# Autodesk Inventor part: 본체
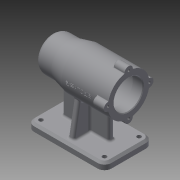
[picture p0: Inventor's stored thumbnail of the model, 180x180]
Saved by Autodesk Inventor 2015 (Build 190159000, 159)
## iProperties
Created: 2019-07
Part Number: 본체
Material: 일반
Document SubType Name: Modeling
Designer: now
Density: 1 g/cm^3
Appearance: 기본값
Author: now
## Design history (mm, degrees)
sketch "스케치1"
  geometry: L1 (-56, 35)-(56, 35); L2 (56, 35)-(56, -35); L3 (56, -35)-(-56, -35); L4 (-56, -35)-(-56, 35); L5 (-56, 35)-(56, -35); L6 (56, 35)-(-56, -35); 1 further point
  constraints: 12 end point, 2 midpoint, 2 parallel, 1 horizontal, 1 perpendicular
  dimensions: "d0" = 70 distance of L1.end L2.end; "d1" = 112 distance of L2.end L3.end
extrude "돌출1" new body sketch "스케치1" distance "d2" = 10; taper "d3" = 0 deg
sketch "스케치2"
  geometry: L1 (-46, 25)-(46, 25); L2 (46, 25)-(46, -25); L3 (46, -25)-(-46, -25); L4 (-46, -25)-(-46, 25); L5 (-46, 25)-(46, -25); L6 (46, 25)-(-46, -25); 1 further point
  constraints: 12 end point, 2 midpoint, 2 parallel, 1 horizontal, 1 perpendicular
  dimensions: "d4" = 92 distance of L2.end L3.end; "d5" = 50 distance of L1.end L2.end
hole "구멍1" sketch "스케치2" at (-46, -25), (46, -25), (46, 25), (-46, 25) diameter "d6" = 6; stored, may be unused: countersink angle "d10" = 90 deg, drill point angle "d12" = 118 deg; dims "d7" = 6, "d8" = 4, "d9" = 2, "d11" = 8
fillet "모깎기1" dims "d13" = 10
sketch "스케치3"
  geometry: L1 (-56, 25)-(-56, -25) reference; L2 (-46, -35)-(46, -35) reference; L3 (56, -25)-(56, 25) reference; L4 (-4, -28)-(4, -28); L5 (4, -28)-(4, 28); L6 (4, 28)-(-4, 28); L7 (-4, 28)-(-4, -28); L8 (-4, -28)-(4, 28); L9 (4, -28)-(-4, 28); L10 (-31, 4)-(31, -4); L11 (-36, 4)-(31, 4); L12 (31, 4)-(31, -4); L13 (31, -4)-(-36, -4); L14 (-36, -4)-(-36, 4); L15 (-36, 4)-(31, -4); L16 (31, 4)-(-36, -4); 2 further points
  constraints: 26 end point, 5 midpoint, 4 parallel, 2 horizontal, 2 perpendicular, 1 horizontal alignment
  dimensions: "d14" = 8 distance of L5.end L6.end; "d16" = 7 distance between parallel lines of L4 L2; "d18" = 25 distance between parallel lines of L3 L12; "d19" = 20 distance between parallel lines of L14 L1; "d20" = 8 distance of L11.end L12.end
extrude "돌출2" join sketch "스케치3" distance "d21" = 70; taper "d22" = 0 deg
node "작업 평면3"
sketch "스케치6"
  geometry: L1 (0, 0)-(0, 80); C1 r 30 at (0, 80)
  constraints: 2 end point, 1 centre point, 1 coincident, 1 vertical
  dimensions: "d29" = 80 distance of L1.start L1.end; "d30" = 60 diameter of C1
extrude "돌출4" join sketch "스케치6" distance "d31" = 67; taper "d32" = 0 deg
node "작업 평면5"
  node "작업 평면4"
sketch "스케치9"
  geometry: L1 (56, 10)-(56, 0) reference; L2 (56, 0)-(-56, 0) reference; L3 (-56, 0)-(-56, 10) reference; L4 (-56, 10)-(-31, 10) reference; L5 (-31, 10)-(-31, 50) reference; L6 (-31, 50)-(-56, 50) reference; L7 (-56, 50)-(-56, 110) reference; L8 (-56, 110)-(11, 110) reference; L9 (11, 110)-(11, 80) reference; L10 (11, 80)-(36, 80) reference; L11 (36, 80)-(36, 10) reference; L12 (36, 10)-(56, 10) reference; L13 (11, 80)-(31, 80); L14 (31, 80)-(31, 105); L15 (31, 105)-(11, 110); 1 further point
  constraints: 6 end point, 1 horizontal, 1 perpendicular
  dimensions: "d37" = 25 distance of L13.end L14.end; "d38" = 20 distance between parallel lines of L9 L14
revolve "회전1" sketch "스케치9" stored, may be unused: angle "d39" = 90 deg
sketch "스케치10"
  geometry: C1 r 25 at (0, 0); A1 r 25 centre (0, 0) between (-24.678, -4) and (-24.678, 4) reference; 1 further point
  constraints: 1 centre point, 1 coincident
  dimensions: "d40" = 50 diameter of C1
extrude "돌출5" join sketch "스케치10" distance "d41" = 25; taper "d42" = 0 deg
feature "면 기울기1" dims angle "d43" = 10 deg
hole "구멍2" diameter "d46" = 42; stored, may be unused: countersink angle "d50" = 90 deg, drill point angle "d52" = 0 deg; dims "d47" = 6, "d48" = 4, "d49" = 2, "d51" = 15, "d64" = 10, "d65" = 10
hole "구멍3" diameter "d57" = 48; stored, may be unused: countersink angle "d61" = 90 deg, drill point angle "d63" = 0 deg; dims "d55" = 10, "d56" = 10, "d58" = 6, "d59" = 4, "d60" = 2, "d62" = 54
hole "구멍4" diameter "d68" = 42; stored, may be unused: countersink angle "d72" = 90 deg, drill point angle "d74" = 0 deg; dims "d66" = 10, "d67" = 10, "d69" = 6, "d70" = 4, "d71" = 2, "d73" = 12
hole "구멍5" diameter "d77" = 35; stored, may be unused: countersink angle "d81" = 90 deg, drill point angle "d83" = 0 deg; dims "d75" = 10, "d76" = 10, "d78" = 6, "d79" = 4, "d80" = 2, "d82" = 18
hole "구멍6" diameter "d86" = 32; stored, may be unused: countersink angle "d90" = 90 deg, drill point angle "d92" = 0 deg; dims "d84" = 10, "d85" = 10, "d87" = 6, "d88" = 4, "d89" = 2, "d91" = 4
hole "구멍7" diameter "d95" = 21; stored, may be unused: countersink angle "d99" = 90 deg, drill point angle "d101" = 0 deg; dims "d93" = 10, "d94" = 10, "d96" = 6, "d97" = 4, "d98" = 2, "d100" = 3
fillet "모깎기2" dims "d102" = 0.3
fillet "모깎기3" dims "d103" = 3
sketch "스케치11"
  geometry: C1 r 6 at (-30, 0); 2 further points
  constraints: 1 centre point, 1 horizontal alignment, 1 other
  dimensions: "d104" = 12 diameter of C1
extrude "돌출6" join sketch "스케치11" distance "d105" = 16; taper "d106" = 0 deg
sketch "스케치12"
  geometry: A1 r 6 centre (-110, 0) between (-109.4, 5.97) and (-109.4, -5.97) reference; A2 r 6 centre (-80, -30) between (-85.97, -29.4) and (-74.03, -29.4) reference; A3 r 6 centre (-50, 0) between (-50.6, -5.97) and (-50.6, 5.97) reference; A4 r 6 centre (-80, 30) between (-74.03, 29.4) and (-85.97, 29.4) reference; 1 further point
hole "구멍8" sketch "스케치12" at (-110, 0), (-80, -30), (-50, 0), (-80, 30) diameter "d110" = 3.242; stored, may be unused: countersink angle "d114" = 90 deg, drill point angle "d116" = 118 deg; dims "d111" = 8, "d112" = 4, "d113" = 2, "d115" = 11
fillet "모깎기4" dims "d117" = 1
fillet "모깎기5" dims "d118" = 10
fillet "모깎기6" dims "d119" = 1
chamfer "모따기1" distance "d120" = 3; stored, may be unused: second distance "d121" = 2, angle "d122" = 45 deg
fillet "모깎기7" dims "d123" = 3
fillet "모깎기8" dims "d124" = 3
fillet "모깎기9" dims "d125" = 3
chamfer "모따기2" distance "d126" = 1; stored, may be unused: second distance "d127" = 2, angle "d128" = 45 deg
node "작업 평면6"
sketch "스케치13"
  geometry: L1 (63.073, 80)-(-60.986, 80); L2 (46, 0)-(-46, 0) reference; L3 (56, 109.226)-(56, 86.771) reference; 2 further points
  constraints: 2 end point, 1 horizontal, 1 point on line, 1 other
  dimensions: "d130" = 80 distance between parallel lines of L1 L2; "d131" = 42 distance from line of point (14, 80) L3
feature "엠보싱1" sketch "스케치13" dims "d132" = 0.5, "d133" = 0
node "솔리드1"
pattern_circular "원형 패턴1" dims angle "d108" = 360 deg
node "절단 모서리 투영1"
other parameters: "d28" = 56, "d33" = -67, "d129" = -30.5
